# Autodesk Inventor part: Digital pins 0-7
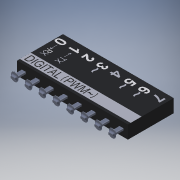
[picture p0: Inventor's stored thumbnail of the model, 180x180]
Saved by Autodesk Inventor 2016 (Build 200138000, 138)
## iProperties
Created: 2018-03
Part Number: Digital pins 0-7
Material: Générique
Document SubType Name: Modeling
Designer: Bruno
Density: 1 g/cm^3
Appearance: Par défaut
Author: Bruno
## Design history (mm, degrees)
feature "Composite1"
body "Srf1"
